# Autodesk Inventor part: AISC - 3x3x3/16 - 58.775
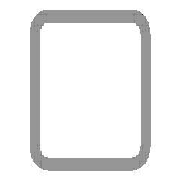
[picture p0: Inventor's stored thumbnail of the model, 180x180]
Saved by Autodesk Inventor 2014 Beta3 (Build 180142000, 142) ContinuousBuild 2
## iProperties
IsCustomPart: 1
Created: 2011-01
Part Number: AISC - 3x3x3/16 - 58.775
Material: Steel, Mild
Description: Tube
Document SubType Name: Modeling
Standard: ANSI
Designer: Beta-8540w
Standards Organization: ANSI
Language: en-US
Size Designation: 3x3x3/16
Categories: <MemberInstance><Categories><Category DisplayName="Structural Shapes" InternalName="089c4875-fa83-4c05-b084-43b9cc11f5ed" Mnemonic="GRDR"><CategoryParameter Dis
Stock Number: 3x3x3/16
Density: 7.86 g/cm^3
Appearance: Steel
_CCFamilyMember: 9
_CCFamilyDisplayName: ANSI AISC (Square) - Tube
_FrameMemberDoc: Frame Member File
_Version: 15.0.0
_GetPNFromCC: 1
G_L: 58.775 in
G_W: 3.000 in
G_H: 3.000 in
+4D71DD38-6577-4695-BB34-97209268B762+CUTDETAIL1: Cut
Author: Beta-8540w
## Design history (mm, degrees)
node "Start plane"
node "End plane"
sketch "Sketch"
  geometry: L1 (-38.1, -28.575)-(-38.1, 28.575); L2 (-28.575, 38.1)-(28.575, 38.1); L3 (38.1, 28.575)-(38.1, -28.575); L4 (28.575, -38.1)-(-28.575, -38.1); L5 (-28.575, 33.337)-(28.575, 33.338); L6 (33.338, 28.575)-(33.338, -28.575); L7 (28.575, -33.337)-(-28.575, -33.338); L8 (-33.338, -28.575)-(-33.338, 28.575); L9 (0, 56.102)-(0, -56.102) reference; L10 (-56.102, 0)-(56.102, 0) reference; A1 r 9.525 centre (-28.575, -28.575) between (-38.1, -28.575) and (-28.575, -38.1); A2 r 9.525 centre (-28.575, 28.575) between (-28.575, 38.1) and (-38.1, 28.575); A3 r 9.525 centre (28.575, 28.575) between (38.1, 28.575) and (28.575, 38.1); A4 r 9.525 centre (28.575, -28.575) between (28.575, -38.1) and (38.1, -28.575); A5 r 4.763 centre (-28.575, 28.575) between (-28.575, 33.337) and (-33.338, 28.575); A6 r 4.763 centre (28.575, 28.575) between (33.338, 28.575) and (28.575, 33.338); A7 r 4.763 centre (28.575, -28.575) between (28.575, -33.337) and (33.338, -28.575); A8 r 4.763 centre (-28.575, -28.575) between (-33.338, -28.575) and (-28.575, -33.338)
  constraints: 16 end point, 16 point on circle, 8 centre point, 8 tangent, 4 parallel, 3 equal radius, 2 perpendicular, 7 other
  dimensions: "d10" = 76.2 distance between parallel lines of L2 L4 (= G_H); "d11" = 76.2 distance between parallel lines of L1 L3 (= G_W); "d12" = 4.7625 distance between parallel lines of L3 L6 (= G_T); "d15" = 38.1 distance between parallel lines of L2 L10 (= 0.5 x d10); "d16" = 38.1 distance between parallel lines of L9 L3 (= 0.5 x d11); "d17" = 9.525 radius of A1 (= G_IR)
extrude "Body" new body sketch "Sketch" stored distance "d3" = 1492.89148 (= G_L); taper "d4" = 0 deg
node "Driven Length"
  sketch "Sketch3"
    geometry: L1 (0, 0)-(10, 0) reference
    constraints: 2 end point, 1 horizontal
  workplane "Work Plane3"
  sketch "Sketch4"
    geometry: L1 (-2, 31.109)-(12, 31.109) reference; L2 (-2, 1524)-(12, 1524) reference
    dimensions: "d19" = 1492.89148 distance between parallel lines of L1 L2 (derived)
workplane "Work Plane4"
split "Split1"
body "Solid1"
other parameters: "G_W" = 76.2 [user parameter; used in 1 equation term], "G_H" = 76.2 [user parameter; used in 1 equation term], "G_T" = 4.7625 [user parameter; used in 1 equation term], "G_IR" = 9.525 [user parameter; used in 1 equation term], "G_L" = 1492.89148 (= d19) [user parameter; used in 1 equation term], "G_OFFSET_START" = -31.10852 [user parameter; used in 1 equation term], "G_OFFSET_END" = 0 [user parameter; used in 1 equation term], "d13" = 31.10852 (= -G_OFFSET_START), "d14" = 1524 (= G_OFFSET_END + B_L), "B_L" = 1524 [user parameter; used in 1 equation term], "d18" = 90 deg
